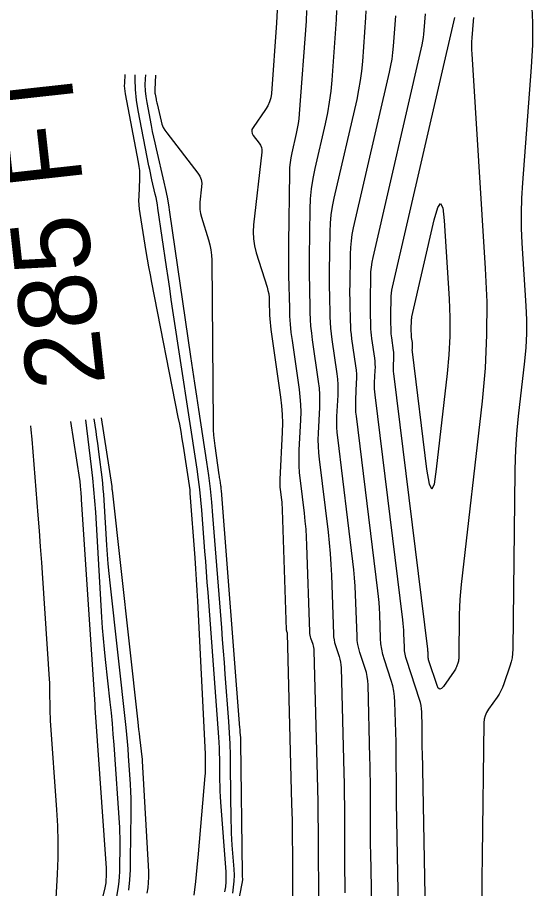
# Model space of a CAD drawing. Extents: x 1768942 to 1774819, y 723037 to 732099.
# Drawn here: x 1770861.8 to 1770901.5, y 724172.9 to 724240.1 of the extents above; entities that cross this region are included whole.
import ezdxf

# ---------------------------------------------------------------- set-up
doc = ezdxf.new("R2010")
doc.units = 0
doc.layers.add('R_Contour Annot', color=7, linetype='Continuous')
doc.layers.add('R_Contours', color=7, linetype='Continuous')

msp = doc.modelspace()

# ---------------------------------------------------------------- linework, layer by layer
at = {"layer": 'R_Contours'}
for points in [[(1770901.466, 724241.457), (1770901.538, 724239.735), (1770901.528, 724238.012), (1770901.436, 724236.287), (1770900.749, 724227.354), (1770900.68, 724226.191), (1770900.652, 724225.029), (1770900.664, 724223.866), (1770900.717, 724222.702), (1770901.023, 724217.86), (1770901.067, 724216.791), (1770901.064, 724215.724), (1770901.014, 724214.659), (1770900.916, 724213.594), (1770900.433, 724209.338), (1770900.326, 724208.273), (1770900.246, 724207.206), (1770900.193, 724206.138), (1770900.168, 724205.068), (1770900.013, 724191.362), (1770899.996, 724191.027), (1770899.953, 724190.695), (1770899.884, 724190.369), (1770899.788, 724190.046), (1770899.322, 724188.673), (1770899.22, 724188.404), (1770899.099, 724188.145), (1770898.959, 724187.896), (1770898.801, 724187.656), (1770898.132, 724186.716), (1770897.985, 724186.474), (1770897.879, 724186.219), (1770897.813, 724185.951), (1770897.789, 724185.669), (1770897.636, 724175.438), (1770897.618, 724173.636), (1770897.615, 724171.835)], [(1770881.817, 724240.707), (1770881.784, 724239.712), (1770881.383, 724234.273), (1770881.336, 724233.937), (1770881.246, 724233.617), (1770881.112, 724233.313), (1770880.935, 724233.024), (1770879.965, 724231.649), (1770879.883, 724231.493), (1770879.858, 724231.338), (1770879.89, 724231.185), (1770879.979, 724231.033), (1770880.448, 724230.428), (1770880.548, 724230.272), (1770880.613, 724230.106), (1770880.643, 724229.93), (1770880.639, 724229.745), (1770880.006, 724224.133), (1770879.972, 724223.584), (1770879.996, 724223.04), (1770880.076, 724222.502), (1770880.213, 724221.97), (1770881.044, 724219.316), (1770881.117, 724219.052), (1770881.171, 724218.784), (1770881.205, 724218.514), (1770881.221, 724218.241), (1770881.245, 724217.141), (1770881.255, 724216.866), (1770881.274, 724216.592), (1770881.301, 724216.319), (1770881.336, 724216.046), (1770882.091, 724210.814), (1770882.171, 724210.143), (1770882.219, 724209.471), (1770882.234, 724208.798), (1770882.216, 724208.123), (1770882.03, 724204.46), (1770882.024, 724204.264), (1770882.027, 724204.068), (1770882.038, 724203.873), (1770882.058, 724203.678), (1770882.154, 724202.897), (1770882.176, 724202.702), (1770882.194, 724202.506), (1770882.207, 724202.31), (1770882.216, 724202.114), (1770882.529, 724192.861), (1770882.531, 724192.835), (1770882.535, 724192.81), (1770882.54, 724192.784), (1770882.548, 724192.759), (1770882.58, 724192.66), (1770882.588, 724192.635), (1770882.593, 724192.609), (1770882.597, 724192.584), (1770882.598, 724192.558), (1770882.943, 724179.415), (1770882.973, 724178.12), (1770882.995, 724176.824), (1770883.01, 724175.527), (1770883.017, 724174.231), (1770883.033, 724167.451)], [(1770885.029, 724172.055), (1770885.018, 724176.331), (1770885.013, 724177.4), (1770885, 724178.469), (1770884.982, 724179.538), (1770884.957, 724180.607), (1770884.678, 724191.238), (1770884.67, 724191.363), (1770884.654, 724191.486), (1770884.628, 724191.607), (1770884.593, 724191.727), (1770884.436, 724192.204), (1770884.401, 724192.324), (1770884.375, 724192.446), (1770884.357, 724192.569), (1770884.349, 724192.693), (1770884.122, 724199.384), (1770884.094, 724200.003), (1770884.052, 724200.622), (1770883.997, 724201.239), (1770883.928, 724201.855), (1770883.617, 724204.38), (1770883.558, 724204.965), (1770883.524, 724205.55), (1770883.516, 724206.137), (1770883.533, 724206.724), (1770883.652, 724209.076), (1770883.668, 724209.663), (1770883.655, 724210.249), (1770883.613, 724210.833), (1770883.544, 724211.417), (1770882.997, 724215.202), (1770882.917, 724215.823), (1770882.856, 724216.445), (1770882.814, 724217.069), (1770882.791, 724217.694), (1770882.736, 724220.199), (1770882.725, 724220.825), (1770882.719, 724221.451), (1770882.719, 724222.077), (1770882.725, 724222.703), (1770882.797, 724228.165), (1770882.812, 724228.548), (1770882.848, 724228.93), (1770882.904, 724229.308), (1770882.98, 724229.685), (1770883.326, 724231.185), (1770883.406, 724231.561), (1770883.47, 724231.94), (1770883.52, 724232.32), (1770883.556, 724232.703), (1770884.083, 724239.851), (1770884.11, 724240.686)], [(1770886.404, 724240.664), (1770886.381, 724239.989), (1770886.036, 724235.304), (1770885.957, 724234.452), (1770885.845, 724233.605), (1770885.701, 724232.763), (1770885.525, 724231.926), (1770884.728, 724228.468), (1770884.57, 724227.69), (1770884.454, 724226.907), (1770884.38, 724226.119), (1770884.349, 724225.326), (1770884.3, 724221.618), (1770884.295, 724221.086), (1770884.295, 724220.553), (1770884.3, 724220.021), (1770884.309, 724219.488), (1770884.356, 724217.358), (1770884.376, 724216.826), (1770884.411, 724216.296), (1770884.463, 724215.767), (1770884.531, 724215.239), (1770884.996, 724212.02), (1770885.056, 724211.524), (1770885.091, 724211.026), (1770885.102, 724210.528), (1770885.088, 724210.029), (1770884.987, 724208.029), (1770884.972, 724207.529), (1770884.98, 724207.03), (1770885.008, 724206.532), (1770885.059, 724206.035), (1770885.754, 724200.395), (1770885.846, 724199.567), (1770885.921, 724198.738), (1770885.976, 724197.907), (1770886.014, 724197.074), (1770886.168, 724192.525), (1770886.184, 724192.302), (1770886.215, 724192.082), (1770886.262, 724191.864), (1770886.324, 724191.649), (1770886.606, 724190.795), (1770886.668, 724190.58), (1770886.714, 724190.363), (1770886.744, 724190.142), (1770886.758, 724189.919), (1770886.971, 724181.799), (1770886.991, 724180.957), (1770887.005, 724180.115), (1770887.015, 724179.274), (1770887.019, 724178.432), (1770887.027, 724175.064), (1770887.031, 724174.222), (1770887.038, 724173.38), (1770887.049, 724172.538)], [(1770889.454, 724154.449), (1770889.053, 724175.614), (1770889.042, 724176.229), (1770889.034, 724176.844), (1770889.029, 724177.458), (1770889.026, 724178.073), (1770889.02, 724180.532), (1770889.017, 724181.147), (1770889.01, 724181.761), (1770889, 724182.376), (1770888.985, 724182.99), (1770888.838, 724188.6), (1770888.818, 724188.921), (1770888.775, 724189.239), (1770888.708, 724189.553), (1770888.618, 724189.863), (1770888.212, 724191.094), (1770888.122, 724191.404), (1770888.055, 724191.718), (1770888.01, 724192.035), (1770887.988, 724192.357), (1770887.879, 724195.57), (1770887.85, 724196.213), (1770887.807, 724196.855), (1770887.749, 724197.496), (1770887.678, 724198.135), (1770886.5, 724207.691), (1770886.459, 724208.1), (1770886.435, 724208.511), (1770886.429, 724208.922), (1770886.441, 724209.334), (1770886.525, 724210.982), (1770886.536, 724211.393), (1770886.527, 724211.804), (1770886.498, 724212.214), (1770886.449, 724212.622), (1770886.066, 724215.275), (1770886.01, 724215.71), (1770885.967, 724216.147), (1770885.937, 724216.584), (1770885.921, 724217.022), (1770885.882, 724218.777), (1770885.875, 724219.216), (1770885.871, 724219.655), (1770885.871, 724220.094), (1770885.875, 724220.533), (1770885.915, 724223.589), (1770885.941, 724224.242), (1770886.002, 724224.892), (1770886.097, 724225.537), (1770886.227, 724226.178), (1770887.988, 724233.813), (1770888.141, 724234.536), (1770888.265, 724235.263), (1770888.361, 724235.995), (1770888.43, 724236.731), (1770888.68, 724240.128), (1770888.697, 724240.642)], [(1770891.584, 724150.923), (1770891.042, 724179.532), (1770891.035, 724179.919), (1770891.03, 724180.307), (1770891.027, 724180.694), (1770891.025, 724181.082), (1770891.022, 724182.632), (1770891.02, 724183.02), (1770891.015, 724183.407), (1770891.008, 724183.795), (1770890.999, 724184.182), (1770890.918, 724187.28), (1770890.892, 724187.701), (1770890.835, 724188.116), (1770890.748, 724188.526), (1770890.631, 724188.931), (1770890.101, 724190.539), (1770889.983, 724190.944), (1770889.895, 724191.354), (1770889.836, 724191.769), (1770889.807, 724192.189), (1770889.743, 724194.066), (1770889.723, 724194.52), (1770889.693, 724194.972), (1770889.652, 724195.424), (1770889.602, 724195.875), (1770887.942, 724209.346), (1770887.909, 724209.668), (1770887.891, 724209.991), (1770887.886, 724210.314), (1770887.895, 724210.638), (1770887.961, 724211.935), (1770887.97, 724212.258), (1770887.963, 724212.581), (1770887.94, 724212.904), (1770887.901, 724213.225), (1770887.6, 724215.312), (1770887.556, 724215.654), (1770887.522, 724215.997), (1770887.499, 724216.341), (1770887.486, 724216.686), (1770887.456, 724218.067), (1770887.45, 724218.412), (1770887.447, 724218.757), (1770887.447, 724219.102), (1770887.45, 724219.448), (1770887.482, 724221.852), (1770887.502, 724222.366), (1770887.55, 724222.876), (1770887.625, 724223.384), (1770887.727, 724223.888), (1770890.503, 724235.923), (1770890.608, 724236.42), (1770890.693, 724236.921), (1770890.76, 724237.424), (1770890.807, 724237.93), (1770890.979, 724240.266)], [(1770893.715, 724147.397), (1770893.031, 724183.449), (1770893.028, 724183.61), (1770893.026, 724183.77), (1770893.025, 724183.93), (1770893.024, 724184.091), (1770893.023, 724184.732), (1770893.022, 724184.893), (1770893.02, 724185.053), (1770893.017, 724185.213), (1770893.014, 724185.374), (1770892.984, 724186.518), (1770892.968, 724186.76), (1770892.936, 724187), (1770892.886, 724187.236), (1770892.818, 724187.47), (1770891.827, 724190.474), (1770891.754, 724190.727), (1770891.699, 724190.983), (1770891.662, 724191.242), (1770891.644, 724191.505), (1770891.608, 724192.562), (1770891.596, 724192.826), (1770891.578, 724193.09), (1770891.555, 724193.353), (1770891.525, 724193.615), (1770889.384, 724211.001), (1770889.36, 724211.236), (1770889.346, 724211.471), (1770889.343, 724211.707), (1770889.35, 724211.943), (1770889.398, 724212.888), (1770889.404, 724213.124), (1770889.399, 724213.359), (1770889.382, 724213.594), (1770889.354, 724213.828), (1770889.134, 724215.349), (1770889.102, 724215.598), (1770889.078, 724215.848), (1770889.061, 724216.099), (1770889.052, 724216.35), (1770889.029, 724217.356), (1770889.025, 724217.608), (1770889.023, 724217.859), (1770889.023, 724218.111), (1770889.025, 724218.362), (1770889.048, 724220.114), (1770889.063, 724220.489), (1770889.098, 724220.861), (1770889.153, 724221.231), (1770889.227, 724221.598), (1770893.018, 724238.033), (1770893.075, 724238.305), (1770893.121, 724238.578), (1770893.158, 724238.853), (1770893.183, 724239.129), (1770893.277, 724240.405)], [(1770896.967, 724240.14), (1770896.952, 724239.849), (1770896.854, 724238.57), (1770896.835, 724238.26), (1770896.828, 724237.95), (1770896.831, 724237.64), (1770896.845, 724237.33), (1770897.892, 724220.748), (1770897.998, 724218.185), (1770897.99, 724215.625), (1770897.87, 724213.068), (1770897.636, 724210.514), (1770896.03, 724196.356), (1770895.971, 724195.776), (1770895.928, 724195.195), (1770895.899, 724194.613), (1770895.885, 724194.029), (1770895.847, 724190.719), (1770895.843, 724190.624), (1770895.831, 724190.531), (1770895.811, 724190.438), (1770895.784, 724190.347), (1770895.661, 724189.986), (1770895.627, 724189.897), (1770895.587, 724189.811), (1770895.541, 724189.728), (1770895.489, 724189.649), (1770894.653, 724188.475), (1770894.505, 724188.314), (1770894.374, 724188.272), (1770894.262, 724188.351), (1770894.167, 724188.549), (1770893.535, 724190.468), (1770893.514, 724190.54), (1770893.498, 724190.612), (1770893.488, 724190.685), (1770893.483, 724190.759), (1770893.473, 724191.058), (1770893.469, 724191.133), (1770893.464, 724191.207), (1770893.458, 724191.281), (1770893.449, 724191.356), (1770890.825, 724212.656), (1770890.81, 724212.804), (1770890.802, 724212.952), (1770890.8, 724213.1), (1770890.804, 724213.248), (1770890.834, 724213.841), (1770890.838, 724213.989), (1770890.835, 724214.137), (1770890.824, 724214.284), (1770890.807, 724214.431), (1770890.669, 724215.386), (1770890.649, 724215.542), (1770890.633, 724215.699), (1770890.623, 724215.856), (1770890.617, 724216.014), (1770890.603, 724216.646), (1770890.6, 724216.803), (1770890.599, 724216.961), (1770890.599, 724217.119), (1770890.6, 724217.277), (1770890.615, 724218.377), (1770890.624, 724218.612), (1770890.646, 724218.846), (1770890.68, 724219.078), (1770890.727, 724219.308), (1770895.532, 724240.143)], [(1770870.073, 724235.733), (1770870.035, 724235.061), (1770870.029, 724234.856), (1770870.036, 724234.653), (1770870.056, 724234.45), (1770870.089, 724234.248), (1770871.108, 724228.965), (1770871.161, 724228.639), (1770871.194, 724228.311), (1770871.208, 724227.982), (1770871.202, 724227.651), (1770871.138, 724226.326), (1770871.131, 724225.995), (1770871.141, 724225.665), (1770871.169, 724225.336), (1770871.214, 724225.009), (1770871.7, 724222.068), (1770871.801, 724221.469), (1770871.906, 724220.871), (1770872.017, 724220.274), (1770872.131, 724219.678), (1770874.171, 724209.284), (1770874.278, 724208.721), (1770874.38, 724208.157), (1770874.475, 724207.591), (1770874.564, 724207.025), (1770875.073, 724203.667), (1770875.076, 724203.645), (1770875.079, 724203.622), (1770875.081, 724203.6), (1770875.083, 724203.578), (1770875.092, 724203.466), (1770875.095, 724203.421), (1770875.097, 724203.399), (1770875.466, 724198.414), (1770875.526, 724197.575), (1770875.581, 724196.736), (1770875.631, 724195.897), (1770875.676, 724195.058), (1770876.246, 724183.805), (1770876.255, 724183.619), (1770876.262, 724183.434), (1770876.267, 724183.248), (1770876.27, 724183.063), (1770876.279, 724182.321), (1770876.279, 724182.135), (1770876.275, 724181.95), (1770876.265, 724181.765), (1770876.252, 724181.58), (1770875.725, 724175.56), (1770875.626, 724174.495), (1770875.516, 724173.432), (1770875.395, 724172.37)], [(1770877.793, 724172.616), (1770877.855, 724173.004), (1770877.891, 724173.393), (1770877.901, 724173.783), (1770877.885, 724174.175), (1770877.484, 724179.556), (1770877.457, 724179.974), (1770877.436, 724180.391), (1770877.421, 724180.809), (1770877.413, 724181.227), (1770877.394, 724182.901), (1770877.386, 724183.319), (1770877.372, 724183.737), (1770877.35, 724184.154), (1770877.323, 724184.572), (1770876.495, 724195.739), (1770876.435, 724196.534), (1770876.375, 724197.328), (1770876.314, 724198.123), (1770876.253, 724198.917), (1770876.004, 724202.095), (1770875.935, 724202.889), (1770875.851, 724203.681), (1770875.754, 724204.471), (1770875.641, 724205.26), (1770873.784, 724217.517), (1770873.657, 724218.361), (1770873.531, 724219.205), (1770873.406, 724220.049), (1770873.283, 724220.893), (1770872.626, 724225.406), (1770872.583, 724225.681), (1770872.534, 724225.956), (1770872.48, 724226.229), (1770872.419, 724226.502), (1770872.165, 724227.588), (1770872.102, 724227.86), (1770872.043, 724228.133), (1770871.986, 724228.406), (1770871.932, 724228.68), (1770871.107, 724232.956), (1770870.977, 724233.761), (1770870.898, 724234.57), (1770870.869, 724235.383), (1770870.878, 724235.718)], [(1770871.653, 724235.704), (1770871.635, 724235.388), (1770871.622, 724234.933), (1770871.638, 724234.48), (1770871.683, 724234.028), (1770871.755, 724233.579), (1770872.101, 724231.785), (1770872.19, 724231.337), (1770872.283, 724230.89), (1770872.381, 724230.443), (1770872.482, 724229.998), (1770873.085, 724227.422), (1770873.214, 724226.843), (1770873.331, 724226.261), (1770873.435, 724225.678), (1770873.526, 724225.092), (1770875.147, 724213.949), (1770875.297, 724212.928), (1770875.447, 724211.907), (1770875.6, 724210.887), (1770875.754, 724209.867), (1770876.372, 724205.786), (1770876.517, 724204.765), (1770876.644, 724203.741), (1770876.752, 724202.716), (1770876.842, 724201.688), (1770877.52, 724193.004), (1770877.59, 724192.109), (1770877.658, 724191.213), (1770877.726, 724190.318), (1770877.793, 724189.422), (1770878.064, 724185.767), (1770878.121, 724184.907), (1770878.165, 724184.047), (1770878.194, 724183.186), (1770878.211, 724182.325), (1770878.259, 724178.087), (1770878.268, 724177.622), (1770878.284, 724177.157), (1770878.307, 724176.692), (1770878.338, 724176.228), (1770878.476, 724174.372), (1770878.495, 724173.909), (1770878.484, 724173.447), (1770878.441, 724172.988), (1770878.368, 724172.53)], [(1770872.442, 724235.689), (1770872.378, 724234.578), (1770872.376, 724234.483), (1770872.379, 724234.389), (1770872.388, 724234.296), (1770872.403, 724234.202), (1770872.475, 724233.83), (1770872.494, 724233.737), (1770872.513, 724233.644), (1770872.533, 724233.551), (1770872.554, 724233.459), (1770872.865, 724232.131), (1770872.937, 724231.885), (1770873.033, 724231.65), (1770873.154, 724231.428), (1770873.3, 724231.217), (1770875.699, 724228.122), (1770875.854, 724227.879), (1770875.955, 724227.622), (1770876.002, 724227.35), (1770875.996, 724227.063), (1770875.863, 724225.883), (1770875.845, 724225.59), (1770875.857, 724225.299), (1770875.9, 724225.011), (1770875.974, 724224.727), (1770876.523, 724222.974), (1770876.629, 724222.585), (1770876.706, 724222.191), (1770876.753, 724221.793), (1770876.772, 724221.391), (1770876.879, 724208.698), (1770876.889, 724208.286), (1770876.913, 724207.875), (1770876.952, 724207.466), (1770877.004, 724207.057), (1770877.331, 724204.81), (1770877.346, 724204.71), (1770877.361, 724204.609), (1770877.376, 724204.509), (1770877.391, 724204.409), (1770877.451, 724204.008), (1770877.466, 724203.907), (1770877.478, 724203.807), (1770877.489, 724203.706), (1770877.498, 724203.605), (1770878.929, 724185.283), (1770878.936, 724185.19), (1770878.943, 724185.098), (1770878.95, 724185.006), (1770878.957, 724184.913), (1770878.985, 724184.544), (1770878.991, 724184.451), (1770878.995, 724184.359), (1770878.999, 724184.266), (1770879, 724184.174), (1770879.115, 724174.028), (1770879.116, 724173.975), (1770879.118, 724173.922), (1770879.12, 724173.869), (1770879.124, 724173.816), (1770879.14, 724173.604), (1770879.142, 724173.551), (1770879.14, 724173.498), (1770879.136, 724173.446), (1770879.127, 724173.394), (1770878.357, 724169.431)], [(1770871.796, 724172.51), (1770871.864, 724172.925), (1770871.906, 724173.341), (1770871.922, 724173.759), (1770871.912, 724174.18), (1770871.442, 724182.707), (1770871.441, 724182.73), (1770871.439, 724182.753), (1770871.435, 724182.799), (1770871.434, 724182.811), (1770871.433, 724182.822), (1770871.432, 724182.834), (1770871.43, 724182.845), (1770871.226, 724184.569), (1770871.192, 724184.86), (1770871.158, 724185.151), (1770871.125, 724185.442), (1770871.093, 724185.733), (1770869.105, 724203.642), (1770869.103, 724203.659), (1770869.102, 724203.676), (1770869.101, 724203.693), (1770869.099, 724203.71), (1770869.095, 724203.791), (1770869.094, 724203.802), (1770869.093, 724203.812), (1770869.092, 724203.823), (1770869.091, 724203.833), (1770869.086, 724203.874), (1770869.083, 724203.895), (1770869.08, 724203.916), (1770868.275, 724209.21)], [(1770862.787, 724208.605), (1770862.821, 724208.292), (1770862.885, 724207.582), (1770863.356, 724201.71), (1770863.451, 724200.494), (1770863.542, 724199.278), (1770863.629, 724198.061), (1770863.712, 724196.844), (1770864.226, 724189.034), (1770864.242, 724188.77), (1770864.253, 724188.506), (1770864.261, 724188.241), (1770864.265, 724187.977), (1770864.272, 724186.918), (1770864.276, 724186.654), (1770864.284, 724186.39), (1770864.296, 724186.125), (1770864.313, 724185.861), (1770864.798, 724178.953), (1770864.866, 724177.714), (1770864.895, 724176.474), (1770864.886, 724175.234), (1770864.838, 724173.993), (1770864.158, 724161.424)], [(1770865.87, 724208.945), (1770866.57, 724204.454), (1770866.589, 724204.326), (1770866.605, 724204.197), (1770866.619, 724204.068), (1770866.631, 724203.939), (1770866.673, 724203.422), (1770866.683, 724203.293), (1770866.692, 724203.163), (1770866.702, 724203.034), (1770866.71, 724202.905), (1770867.753, 724187.081), (1770867.754, 724187.061), (1770867.755, 724187.041), (1770867.756, 724187.021), (1770867.756, 724187.001), (1770867.756, 724186.921), (1770867.757, 724186.901), (1770867.757, 724186.881), (1770867.758, 724186.861), (1770867.76, 724186.841), (1770868.63, 724174.448), (1770868.637, 724174.321), (1770868.64, 724174.194), (1770868.639, 724174.067), (1770868.634, 724173.94), (1770868.607, 724173.432), (1770868.597, 724173.305), (1770868.582, 724173.179), (1770868.56, 724173.054), (1770868.533, 724172.93), (1770865.047, 724158.7)], [(1770867.032, 724209.073), (1770867.475, 724205.427), (1770867.574, 724204.554), (1770867.66, 724203.68), (1770867.733, 724202.805), (1770867.792, 724201.929), (1770868.277, 724193.84), (1770868.331, 724193.016), (1770868.396, 724192.194), (1770868.472, 724191.372), (1770868.558, 724190.551), (1770868.922, 724187.27), (1770869.008, 724186.449), (1770869.086, 724185.627), (1770869.155, 724184.805), (1770869.215, 724183.982), (1770869.647, 724177.59), (1770869.669, 724177.211), (1770869.683, 724176.832), (1770869.689, 724176.453), (1770869.688, 724176.073), (1770869.667, 724174.554), (1770869.656, 724174.175), (1770869.631, 724173.797), (1770869.593, 724173.42), (1770869.543, 724173.044), (1770869.076, 724169.985)], [(1770867.677, 724209.144), (1770867.828, 724208.156), (1770867.893, 724207.716), (1770867.955, 724207.276), (1770868.013, 724206.836), (1770868.068, 724206.395), (1770868.283, 724204.63), (1770868.333, 724204.188), (1770868.377, 724203.746), (1770868.413, 724203.304), (1770868.443, 724202.86), (1770868.651, 724199.387), (1770868.7, 724198.661), (1770868.757, 724197.936), (1770868.823, 724197.211), (1770868.899, 724196.487), (1770870.139, 724185.315), (1770870.197, 724184.768), (1770870.248, 724184.22), (1770870.294, 724183.672), (1770870.334, 724183.123), (1770870.483, 724180.928), (1770870.514, 724180.378), (1770870.535, 724179.829), (1770870.544, 724179.279), (1770870.542, 724178.729), (1770870.493, 724175.107), (1770870.469, 724174.322), (1770870.417, 724173.538), (1770870.339, 724172.756)]]:
    msp.add_lwpolyline(points, dxfattribs=at)
msp.add_lwpolyline([(1770892.261, 724214.372), (1770892.257, 724214.432), (1770892.256, 724214.492), (1770892.258, 724214.552), (1770892.27, 724214.794), (1770892.272, 724214.854), (1770892.271, 724214.914), (1770892.266, 724214.974), (1770892.259, 724215.034), (1770892.203, 724215.422), (1770892.195, 724215.486), (1770892.189, 724215.55), (1770892.184, 724215.614), (1770892.182, 724215.678), (1770892.176, 724215.935), (1770892.175, 724215.999), (1770892.175, 724216.063), (1770892.175, 724216.128), (1770892.175, 724216.192), (1770892.181, 724216.639), (1770892.185, 724216.735), (1770892.194, 724216.83), (1770892.208, 724216.925), (1770892.227, 724217.018), (1770893.954, 724224.509), (1770894.223, 724225.465), (1770894.438, 724225.773), (1770894.601, 724225.434), (1770894.71, 724224.447), (1770895.092, 724218.405), (1770895.151, 724216.962), (1770895.147, 724215.521), (1770895.079, 724214.081), (1770894.948, 724212.643), (1770894.109, 724205.25), (1770893.933, 724204.1), (1770893.753, 724203.717), (1770893.57, 724204.099), (1770893.384, 724205.247), (1770892.267, 724214.312)], close=True, dxfattribs=at)

# ---------------------------------------------------------------- texts
at = {"layer": 'R_Contour Annot'}
msp.add_text('285 FT', height=6, rotation=96.2962, dxfattribs=at).set_placement((1770868.568, 724211.833))

doc.saveas('drawing.dxf')
